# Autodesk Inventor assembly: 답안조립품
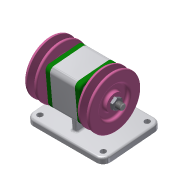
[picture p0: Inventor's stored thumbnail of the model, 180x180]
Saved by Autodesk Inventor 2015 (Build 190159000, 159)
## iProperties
Created: 2020-11
Part Number: 답안조립품
Document SubType Name: Assembly
Designer: pc-04
Author: pc-04
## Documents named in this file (10)
- C:\Users\pc-04\Desktop\답안조립품.iam
- C:\Users\pc-04\Desktop\1.본체.ipt
- C:\Users\pc-04\Desktop\너트 M10x1.ipt
- C:\Users\pc-04\Desktop\베어링 6004.ipt
- C:\Users\pc-04\Desktop\볼트 M4.ipt
- C:\Users\pc-04\Desktop\오일 실 17 30 5.ipt
- C:\Users\pc-04\Desktop\축.ipt
- C:\Users\pc-04\Desktop\커버.ipt
- C:\Users\pc-04\Desktop\키 5 x 5 x 12.ipt
- C:\Users\pc-04\Desktop\V-벨트풀리.ipt
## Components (3 placed, 2 different names)
1. 1.본체:1
2. V-벨트풀리:1 — 각도:2
3. V-벨트풀리:2
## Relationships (1: Angle 1)
- 각도:2 [Angle]: V-벨트풀리:1
